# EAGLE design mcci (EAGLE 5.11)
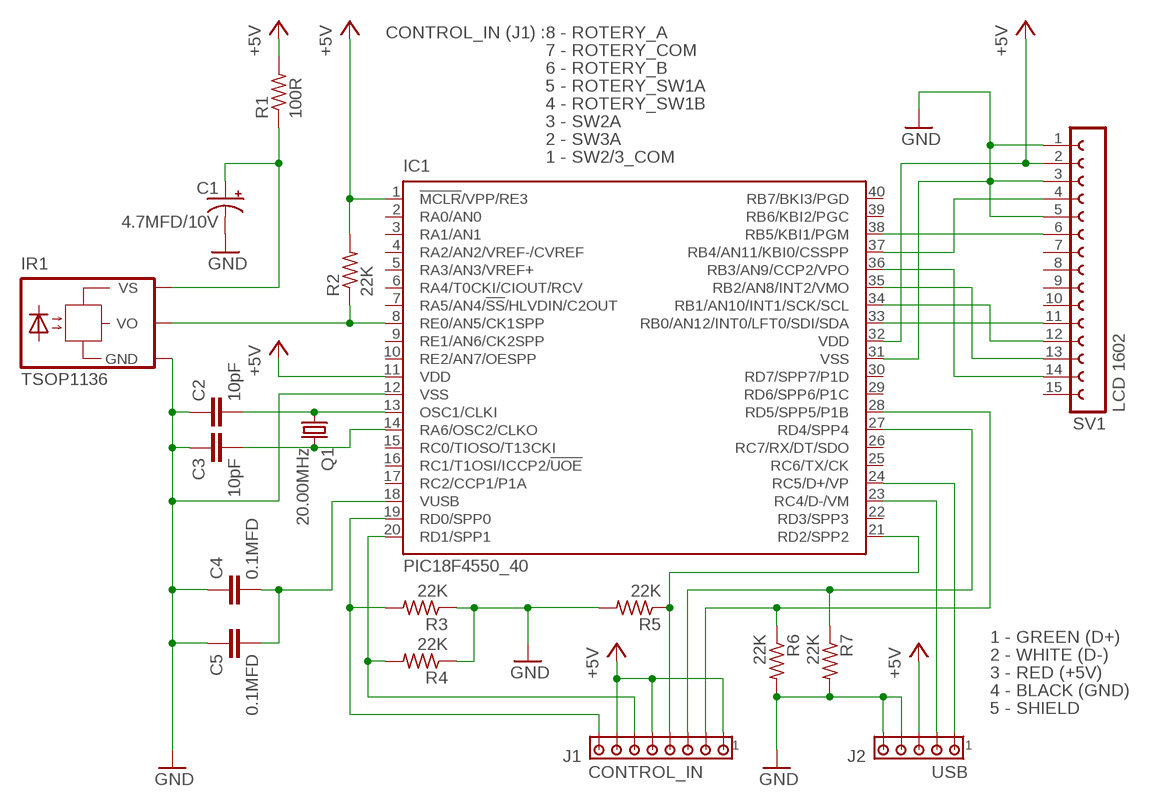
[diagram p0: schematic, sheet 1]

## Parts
C1  4.7MFD/10V  CPOL-USE2-5  [E2-5]
C2  10pF  C2.5/2  [C2.5-2]
C3  10pF  C2.5/2  [C2.5-2]
C4  0.1MFD  C5/3.5  [C5B3.5]
C5  0.1MFD  C5/3.5  [C5B3.5]
IC1  PIC18F4550_40  [DIL40]
IR1  TSOP1136  TSOP1736TB1  [TSOP17_TB1]
J1  MTA08-100  [10X08MTA]
J2  MTA05-100  [10X05MTA]
Q1  20.00MHz  CRYSTALHC49U-V  [HC49U-V]
R1  100R  R-US_0204/7  [0204/7]
R2  22K  R-US_0204/7  [0204/7]
R3  22K  R-US_0204/7  [0204/7]
R4  22K  R-US_0204/7  [0204/7]
R5  22K  R-US_0204/7  [0204/7]
R6  22K  R-US_0204/7  [0204/7]
R7  22K  R-US_0204/7  [0204/7]
SV1  FE15-1  [FE15]

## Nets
+5V: IC1.1(!MCLR!/VPP/RE3) IC1.11(VDD) IC1.32(VDD) J1.1 J1.5 J1.7 J2.3 R1.2 R2.2 SV1.2
GND: C1.- C2.1 C3.1 C4.1 C5.1 IC1.12(VSS) IC1.31(VSS) IR1.GND J2.4 J2.5 R3.1 R4.1 R5.2 R6.2 R7.2 SV1.1 SV1.3 SV1.5
N$1: C1.+ IR1.VS R1.1
N$2: IC1.19(RD0/SPP0) J1.8 R3.2
N$3: IC1.8(RE0/AN5/CK1SPP) IR1.VO R2.1
N$4: C2.2 IC1.13(OSC1/CLKI) Q1.1
N$5: C3.2 IC1.14(RA6/OSC2/CLKO) Q1.2
N$6: C4.2 C5.2 IC1.18(VUSB)
N$7: IC1.20(RD1/SPP1) J1.6 R4.2
N$8: IC1.23(RC4/D-/VM) J2.2
N$9: IC1.21(RD2/SPP2) J1.4 R5.1
N$10: IC1.24(RC5/D+/VP) J2.1
N$11: IC1.27(RD4/SPP4) J1.3 R7.1
N$12: IC1.28(RD5/SPP5/P1B) J1.2 R6.1
N$15: IC1.37(RB4/AN11/KBI0/CSSPP) SV1.4
N$16: IC1.38(RB5/KBI1/PGM) SV1.6
N$17: IC1.36(RB3/AN9/CCP2/VPO) SV1.14
N$18: IC1.35(RB2/AN8/INT2/VMO) SV1.13
N$19: IC1.34(RB1/AN10/INT1/SCK/SCL) SV1.12
N$20: IC1.33(RB0/AN12/INT0/LFT0/SDI/SDA) SV1.11
Unconnected: IC1.2(RA0/AN0) IC1.3(RA1/AN1) IC1.4(RA2/AN2/VREF-/CVREF) IC1.5(RA3/AN3/VREF+) IC1.6(RA4/T0CKI/CIOUT/RCV) IC1.7(RA5/AN4/!SS!/HLVDIN/C2OUT) IC1.9(RE1/AN6/CK2SPP) IC1.10(RE2/AN7/OESPP) IC1.15(RC0/TIOSO/T13CKI) IC1.16(RC1/T1OSI/ICCP2/!UOE) IC1.17(RC2/CCP1/P1A) IC1.22(RD3/SPP3) IC1.25(RC6/TX/CK) IC1.26(RC7/RX/DT/SDO) IC1.29(RD6/SPP6/P1C) IC1.30(RD7/SPP7/P1D) IC1.39(RB6/KBI2/PGC) IC1.40(RB7/BKI3/PGD) SV1.7 SV1.8 SV1.9 SV1.10 SV1.15

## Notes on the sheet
- CONTROL_IN (J1) : | 8 - ROTERY_A
- 7 - ROTERY_COM
- 6 - ROTERY_B
- 5 - ROTERY_SW1A
- 4 - ROTERY_SW1B
- 3 - SW2A
- 2 - SW3A
- 1 - SW2/3_COM
- LCD 1602
- 1 - GREEN (D+)
- 2 - WHITE (D-)
- 3 - RED (+5V)
- 4 - BLACK (GND)
- 5 - SHIELD
- CONTROL_IN | USB

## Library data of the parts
C1 = rcl:CPOL-US: POLARIZED CAPACITOR, American symbol
C2-C5 = capacitor-wima:C: CAPACITOR
IC1 = microchip:PIC18F4*_40: USB Microcontrollers with nanoWatt Technology High-Performance, Enhanced Flash, 28/40/44-Pin, Source: http://ww1.microchip.com/downloads/en/devicedoc/39632c.pdf; MF: MICROCHIP; MPN: PIC18F4550-I/P; OC_FARNELL: 9321357; OC_NEWARK: 74K8623
IR1 = telefunken:TSOP17*TB1: TSOP17..TB1 IR Receiver Modules for Remote Control Systems Source: http://www.vishay.com/docs/82042/82042.pdf; OC_FARNELL: unknown; OC_NEWARK: unknown
J1 = con-amp:MTA08-100: AMP connector; OC_FARNELL: unknown; OC_NEWARK: unknown
J2 = con-amp:MTA05-100: AMP connector; OC_FARNELL: unknown; OC_NEWARK: unknown
Q1 = crystal:CRYSTAL: CRYSTAL; OC_FARNELL: 1666969; OC_NEWARK: unknown
R1-R7 = resistor:R-US_: RESISTOR, American symbol
SV1 = con-lsta:FE15-1: FEMALE HEADER; OC_FARNELL: unknown; OC_NEWARK: unknown

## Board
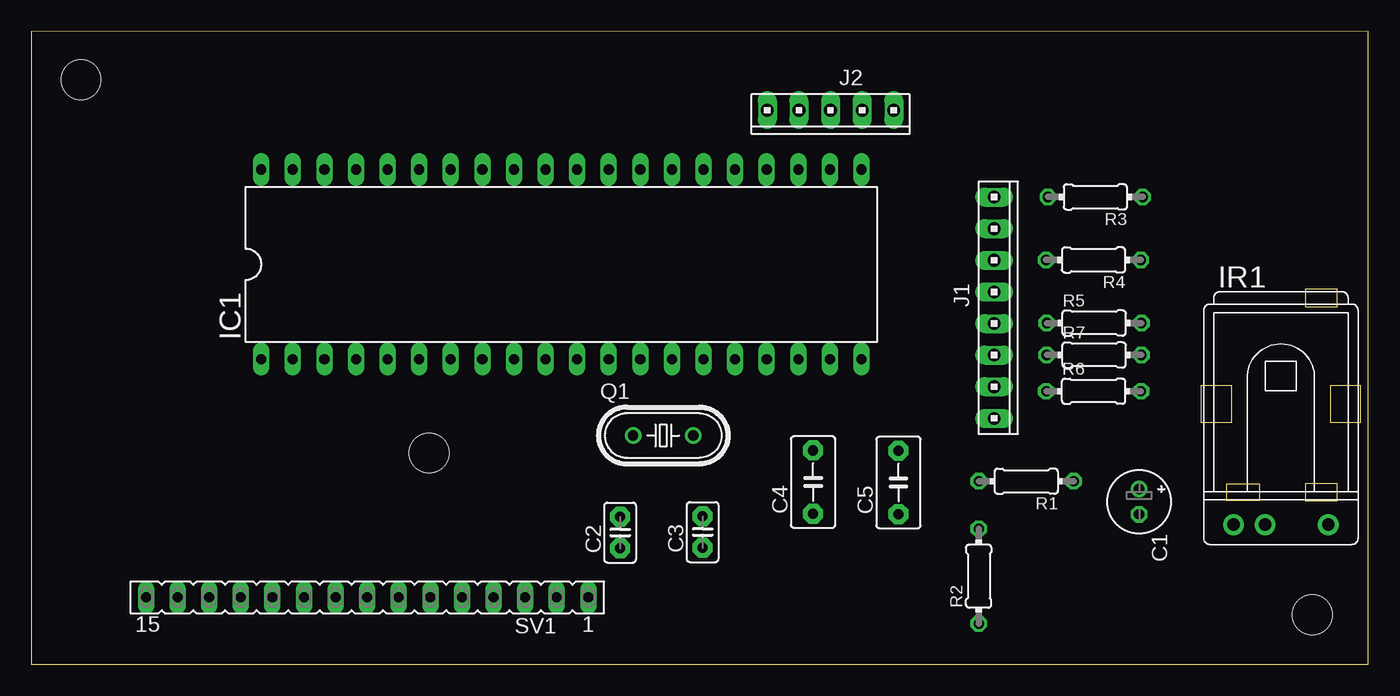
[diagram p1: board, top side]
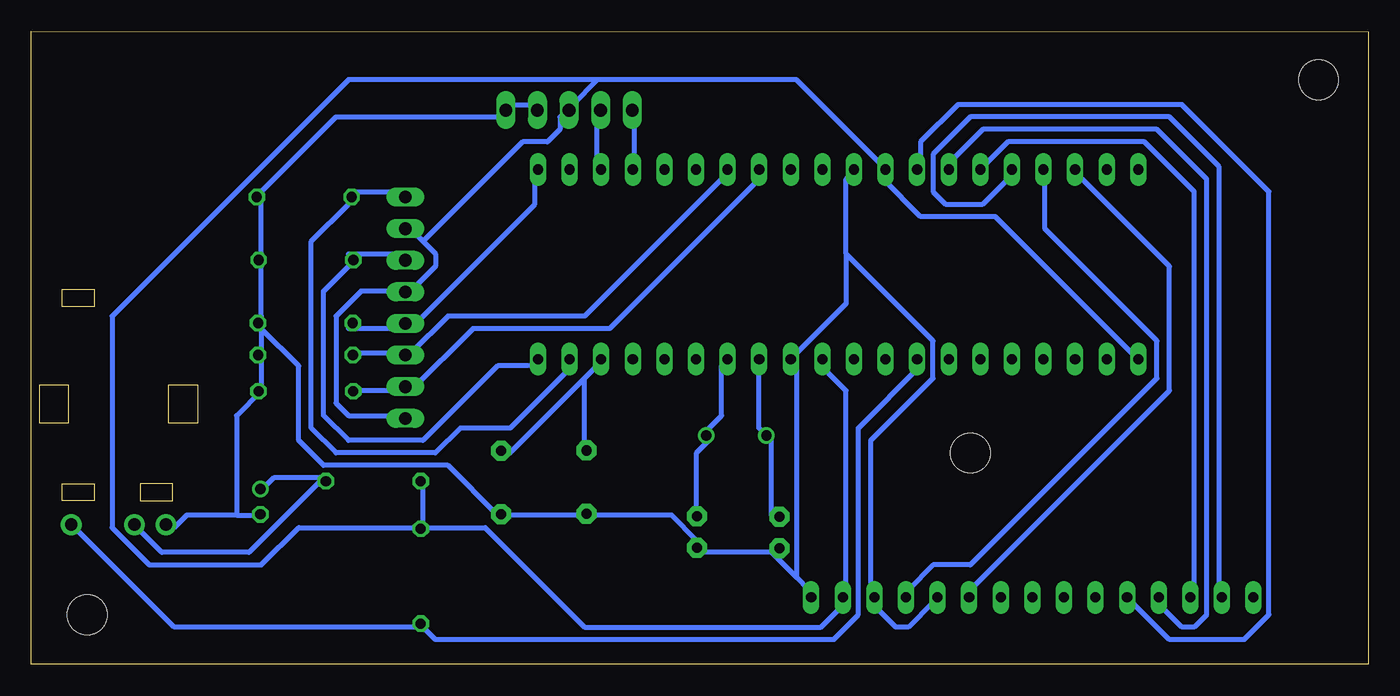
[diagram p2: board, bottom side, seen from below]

Size 107.51 x 50.9 mm. Coordinates in mm from the lower left corner, seen from the top.
Outline: 0,0 107.5,0 107.52,50.9 0,50.85 0,0
Copper layers (1*16): Top 0.035mm / dielectric 1.5mm / Bottom 0.035mm
Design rules "default *": minimum track width 16mil, minimum drill 24mil, track to track 12mil, track to pad 12mil, pad to pad 12mil, via to via 15mil, smd to smd 8mil, copper to edge 40mil, drill to drill 8mil, minimum pad ring 10mil, minimum via ring 8mil, stop-mask expansion 4mil, vias tented up to drill 0mil, thermal gap 10mil

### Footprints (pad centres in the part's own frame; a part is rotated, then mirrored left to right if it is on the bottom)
E2-5 = drill 0.813 pad 1.27 round: + -1.016,0 | drill 0.813 pad 1.27 octagon: - 1.016,0
C2.5-2 = drill 0.813 pad 1.6 octagon: 1 -1.27,0; 2 1.27,0
C5B3.5 = drill 0.813 pad 1.6 octagon: 1 -2.54,0; 2 2.54,0
DRILL_0.1250 = hole 3.175: 0,0
DIL40 = drill 0.813 long: 1 -24.13,-7.62; 2 -21.59,-7.62; 3 -19.05,-7.62; 4 -16.51,-7.62; 5 -13.97,-7.62; 6 -11.43,-7.62; 7 -8.89,-7.62; 8 -6.35,-7.62; 9 -3.81,-7.62; 10 -1.27,-7.62; 11 1.27,-7.62; 12 3.81,-7.62; 13 6.35,-7.62; 14 8.89,-7.62; 15 11.43,-7.62; 16 13.97,-7.62; 17 16.51,-7.62; 18 19.05,-7.62; 19 21.59,-7.62; 20 24.13,-7.62; 21 24.13,7.62; 22 21.59,7.62; 23 19.05,7.62; 24 16.51,7.62; 25 13.97,7.62; 26 11.43,7.62; 27 8.89,7.62; 28 6.35,7.62; 29 3.81,7.62; 30 1.27,7.62; 31 -1.27,7.62; 32 -3.81,7.62; 33 -6.35,7.62; 34 -8.89,7.62; 35 -11.43,7.62; 36 -13.97,7.62; 37 -16.51,7.62; 38 -19.05,7.62; 39 -21.59,7.62; 40 -24.13,7.62
TSOP17_TB1 = drill 1 pad 1.676 round: GND 0,-3.81; VO 0,3.81; VS 0,-1.27
10X08MTA = drill 1.016 long: 1 8.89,0; 2 6.35,0; 3 3.81,0; 4 1.27,0; 5 -1.27,0; 6 -3.81,0; 7 -6.35,0; 8 -8.89,0
10X05MTA = drill 1.016 long: 1 5.08,0; 2 2.54,0; 3 0,0; 4 -2.54,0; 5 -5.08,0
HC49U-V = drill 0.813 round: 1 -2.413,0; 2 2.413,0
0204/7 = drill 0.813 octagon: 1 -3.81,0; 2 3.81,0
FE15 = drill 0.813 long: 1 -17.78,0; 2 -15.24,0; 3 -12.7,0; 4 -10.16,0; 5 -7.62,0; 6 -5.08,0; 7 -2.54,0; 8 0,0; 9 2.54,0; 10 5.08,0; 11 7.62,0; 12 10.16,0; 13 12.7,0; 14 15.24,0; 15 17.78,0

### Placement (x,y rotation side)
C1  89.08,13.08 270 top
C2  47.36,10.6 90 top
C3  53.99,10.64 90 top
C4  62.87,14.66 90 top
C5  69.74,14.63 90 top
E$1  [DRILL_0.1250]  4,47 0 top
E$2  [DRILL_0.1250]  32,17 0 top
E$3  [DRILL_0.1250]  103,4 0 top
IC1  42.63,32.16 0 top
IR1  100.48,11.24 270 top
J1  77.43,28.67 270 top
J2  64.27,44.54 180 top
Q1  50.82,18.4 0 top
R1  80.01,14.73 180 top
R2  76.19,7.1 90 top
R3  85.56,37.57 180 top
R4  85.41,32.51 180 top
R5  85.46,27.44 0 top
R6  85.42,21.96 0 top
R7  85.46,24.87 0 top
SV1  27.02,5.39 180 top

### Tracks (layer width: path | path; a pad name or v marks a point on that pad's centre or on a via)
+5V
  Bottom 0.406: 76,11 76,15 R1.2 | IC1.11 44,24 42,22 42,6 SV1.2 42,5 44,3 63,3 71,11 76,11 | IC1.1 19,25 30,36 36,36 39,39 IC1.32 39,40 46,47 62,47 | J1.1 78,20 82,20 83,21 83,28 81,30 78,30 J1.5 77,30 75,32 75,33 76,34 | 76,34 77,35 J1.7 | 76,34 68,42 66,42 65,43 65,44 J2.3 64,45 62,47 | 76,11 86,11 89,8 98,8 101,11 101,28 82,47 62,47 | 76,11 R2.2
GND
  Bottom 0.406: 91,12 95,12 96,11 IR1.GND | 91,12 89,12 C1.- | J2.4 67,45 69,45 J2.5 70,44 83,44 89,38 | 89,25 89,22 | 89,27 89,25 | 89,25 R7.2 | 89,38 89,33 R4.1 89,32 89,28 R5.2 89,27 | 89,38 R3.1 | 91,12 91,20 89,22 | 89,22 R6.2 | 63,12 69,12 C5.1 70,12 74,16 84,16 86,18 86,24 89,27 | SV1.5 35,5 37,3 38,3 40,5 SV1.3 40,6 40,18 35,23 35,26 42,33 | 46,7 48,9 | 46,7 45,6 SV1.1 | 46,7 46,24 IC1.12 46,25 42,29 42,33 | 42,33 42,39 IC1.31 | 48,9 54,9 C3.1 54,10 56,12 63,12 | 48,9 C2.1 | 63,12 C4.1
N$1
  Bottom 0.406: 84,15 88,15 89,14 C1.+ | 84,15 90,9 97,9 99,11 IR1.VS | R1.1 84,15
N$2
  Bottom 0.406: IC1.19 64,24 69,19 73,19 75,17 83,17 85,19 85,34 82,37 R3.2 82,38 78,38 J1.8
N$3
  Bottom 0.406: 76,3 96,3 104,11 IR1.VO | 76,3 75,2 43,2 41,4 41,19 36,24 IC1.8 | 76,3 R2.1
N$4
  Bottom 0.406: 48,18 48,12 C2.2 | 48,18 49,19 49,24 IC1.13 | 48,18 Q1.1
N$5
  Bottom 0.406: IC1.14 52,24 52,20 53,19 Q1.2 53,18 54,17 54,12 C3.2
N$6
  Bottom 0.406: 63,23 69,17 C5.2 | 63,23 62,24 IC1.18 | 63,23 63,18 C4.2
N$7
  Bottom 0.406: IC1.20 67,24 70,24 76,18 82,18 84,20 84,30 82,32 R4.2 82,33 78,33 J1.6
N$8
  Bottom 0.406: IC1.23 62,40 62,44 J2.2
N$9
  Bottom 0.406: R5.1 82,27 78,27 J1.4 77,27 67,37 67,39 IC1.21
N$10
  Bottom 0.406: IC1.24 59,40 59,44 J2.1
N$11
  Bottom 0.406: IC1.27 52,39 63,28 74,28 77,25 J1.3 78,25 81,25 R7.1
N$12
  Bottom 0.406: R6.1 81,22 78,22 J1.2 77,22 72,27 61,27 49,39 IC1.28
N$15
  Bottom 0.406: IC1.37 26,39 26,35 17,26 17,23 32,8 35,8 37,6 SV1.4
N$16
  Bottom 0.406: SV1.6 32,6 16,22 16,32 23,39 IC1.38
N$17
  Bottom 0.406: SV1.14 12,6 12,40 16,44 32,44 35,41 35,38 34,37 31,37 29,39 IC1.36
N$18
  Bottom 0.406: SV1.13 14,6 14,38 18,42 29,42 31,40 IC1.35
N$19
  Bottom 0.406: SV1.12 17,5 15,3 14,3 13,4 13,39 17,43 31,43 34,40 IC1.34
N$20
  Bottom 0.406: SV1.11 19,5 16,2 10,2 8,4 8,38 15,45 33,45 36,42 36,40 IC1.33

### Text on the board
tValues: USB | CNTRL | LCD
